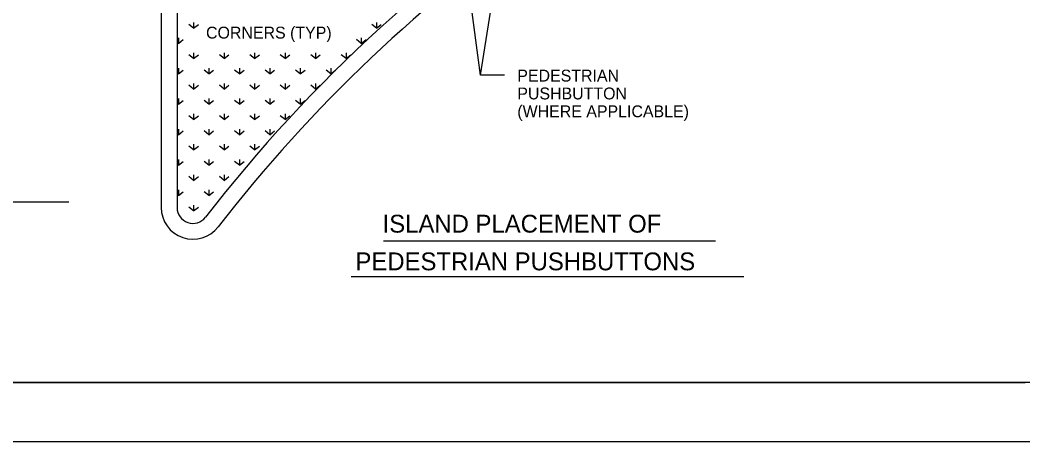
# Model space of a CAD drawing. Extents: x 36 to 940, y -1166 to 1210.
# Drawn here: x 408.6 to 661.3, y -1165.8 to -1059.4 of the extents above; entities that cross this region are included whole.
import ezdxf

# ---------------------------------------------------------------- set-up
doc = ezdxf.new("R2010")
doc.units = 0
for name, color, linetype in [('1', 7, 'Continuous'), ('2', 7, 'Continuous'), ('Default', 7, 'Continuous'), ('PLT-BNDY', 7, 'Continuous')]:
    doc.layers.add(name, color=color, linetype=linetype)

msp = doc.modelspace()

# ---------------------------------------------------------------- linework, layer by layer
at = {"layer": '1'}
for p, q in [((861.86, -1150.83), (75.86, -1150.83)), ((75.86, -1150.83), (661.86, -1150.83))]:
    msp.add_line(p, q, dxfattribs=at)
at = {"layer": '2'}
for p, q in [((524.67, -1073.35), (538.81, -984.29)), ((524.67, -1073.35), (519.57, -1035.44)), ((277.32, -1105.31), (420.95, -1105.31)), ((500.24, -1115.13), (583.82, -1115.13)), ((492.05, -1124.14), (590.98, -1124.14))]:
    msp.add_line(p, q, dxfattribs=at)
at = {"layer": 'Default'}
for p, q in [((444.2, -994.91), (444.2, -1106.71)), ((448.2, -1002.91), (448.2, -1106.71)), ((452.36, -1061.48), (451.16, -1060.52)), ((452.36, -1060.04), (452.36, -1061.48)), ((452.36, -1061.48), (453.56, -1060.52)), ((498.44, -1061.48), (497.24, -1060.52)), ((498.44, -1060.04), (498.44, -1061.48)), ((498.44, -1061.48), (499.64, -1060.52)), ((448.52, -1065.32), (448.2, -1065.07)), ((448.52, -1063.88), (448.52, -1065.32)), ((448.52, -1065.32), (449.72, -1064.36)), ((494.6, -1065.32), (493.4, -1064.36)), ((494.6, -1063.88), (494.6, -1065.32)), ((494.6, -1065.32), (495.8, -1064.36)), ((452.36, -1069.16), (451.16, -1068.2)), ((452.36, -1067.72), (452.36, -1069.16)), ((452.36, -1069.16), (453.56, -1068.2)), ((460.04, -1069.16), (458.84, -1068.2)), ((460.04, -1067.72), (460.04, -1069.16)), ((460.04, -1069.16), (461.24, -1068.2)), ((467.72, -1069.16), (466.52, -1068.2)), ((467.72, -1067.72), (467.72, -1069.16)), ((467.72, -1069.16), (468.92, -1068.2)), ((475.4, -1069.16), (474.2, -1068.2)), ((475.4, -1067.72), (475.4, -1069.16)), ((475.4, -1069.16), (476.6, -1068.2)), ((483.08, -1069.16), (481.88, -1068.2)), ((483.08, -1067.72), (483.08, -1069.16)), ((483.08, -1069.16), (484.28, -1068.2)), ((490.76, -1069.16), (489.56, -1068.2)), ((490.76, -1067.72), (490.76, -1069.16)), ((490.76, -1069.16), (491.96, -1068.2)), ((448.52, -1073), (448.2, -1072.75)), ((448.52, -1071.56), (448.52, -1073)), ((448.52, -1073), (449.72, -1072.04)), ((456.2, -1073), (455, -1072.04)), ((456.2, -1071.56), (456.2, -1073)), ((456.2, -1073), (457.4, -1072.04)), ((463.88, -1073), (462.68, -1072.04)), ((463.88, -1071.56), (463.88, -1073)), ((463.88, -1073), (465.08, -1072.04)), ((471.56, -1073), (470.36, -1072.04)), ((471.56, -1071.56), (471.56, -1073)), ((471.56, -1073), (472.76, -1072.04)), ((479.24, -1073), (478.04, -1072.04)), ((479.24, -1071.56), (479.24, -1073)), ((479.24, -1073), (480.44, -1072.04)), ((486.92, -1073), (485.72, -1072.04)), ((486.92, -1071.56), (486.92, -1073)), ((486.92, -1073), (488.12, -1072.04)), ((530.67, -1073.35), (524.67, -1073.35)), ((452.36, -1076.84), (451.16, -1075.88)), ((452.36, -1075.4), (452.36, -1076.84)), ((452.36, -1076.84), (453.56, -1075.88)), ((460.04, -1076.84), (458.84, -1075.88)), ((460.04, -1075.4), (460.04, -1076.84)), ((460.04, -1076.84), (461.24, -1075.88)), ((467.72, -1076.84), (466.52, -1075.88)), ((467.72, -1075.4), (467.72, -1076.84)), ((467.72, -1076.84), (468.92, -1075.88)), ((475.4, -1076.84), (474.2, -1075.88)), ((475.4, -1075.4), (475.4, -1076.84)), ((475.4, -1076.84), (476.6, -1075.88)), ((483.08, -1076.84), (481.88, -1075.88)), ((483.08, -1075.4), (483.08, -1076.84)), ((483.08, -1076.84), (484.28, -1075.88)), ((448.52, -1080.68), (448.2, -1080.43)), ((448.52, -1079.24), (448.52, -1080.68)), ((448.52, -1080.68), (449.72, -1079.72)), ((456.2, -1080.68), (455, -1079.72)), ((456.2, -1079.24), (456.2, -1080.68)), ((456.2, -1080.68), (457.4, -1079.72)), ((463.88, -1080.68), (462.68, -1079.72)), ((463.88, -1079.24), (463.88, -1080.68)), ((463.88, -1080.68), (465.08, -1079.72)), ((471.56, -1080.68), (470.36, -1079.72)), ((471.56, -1079.24), (471.56, -1080.68)), ((471.56, -1080.68), (472.76, -1079.72)), ((479.24, -1080.68), (478.04, -1079.72)), ((479.24, -1079.24), (479.24, -1080.68)), ((479.24, -1080.68), (480.44, -1079.72)), ((452.36, -1084.52), (451.16, -1083.56)), ((452.36, -1083.08), (452.36, -1084.52)), ((452.36, -1084.52), (453.56, -1083.56)), ((460.04, -1084.52), (458.84, -1083.56)), ((460.04, -1083.08), (460.04, -1084.52)), ((460.04, -1084.52), (461.24, -1083.56)), ((467.72, -1084.52), (466.52, -1083.56)), ((467.72, -1083.08), (467.72, -1084.52)), ((467.72, -1084.52), (468.92, -1083.56)), ((475.4, -1084.52), (474.2, -1083.56)), ((475.4, -1083.08), (475.4, -1084.52)), ((475.4, -1084.52), (476.6, -1083.56)), ((448.52, -1088.36), (448.2, -1088.11)), ((448.52, -1086.92), (448.52, -1088.36)), ((448.52, -1088.36), (449.72, -1087.4)), ((456.2, -1088.36), (455, -1087.4)), ((456.2, -1086.92), (456.2, -1088.36)), ((456.2, -1088.36), (457.4, -1087.4)), ((463.88, -1088.36), (462.68, -1087.4)), ((463.88, -1086.92), (463.88, -1088.36)), ((463.88, -1088.36), (465.08, -1087.4)), ((471.56, -1088.36), (470.36, -1087.4)), ((471.56, -1086.92), (471.56, -1088.36)), ((471.56, -1088.36), (472.76, -1087.4)), ((452.36, -1092.2), (451.16, -1091.24)), ((452.36, -1090.76), (452.36, -1092.2)), ((452.36, -1092.2), (453.56, -1091.24)), ((460.04, -1092.2), (458.84, -1091.24)), ((460.04, -1090.76), (460.04, -1092.2)), ((460.04, -1092.2), (461.24, -1091.24)), ((467.72, -1092.2), (466.52, -1091.24)), ((467.72, -1090.76), (467.72, -1092.2)), ((467.72, -1092.2), (468.92, -1091.24)), ((448.52, -1096.04), (448.2, -1095.79)), ((448.52, -1094.6), (448.52, -1096.04)), ((448.52, -1096.04), (449.72, -1095.08)), ((456.2, -1096.04), (455, -1095.08)), ((456.2, -1094.6), (456.2, -1096.04)), ((456.2, -1096.04), (457.4, -1095.08)), ((463.88, -1096.04), (462.68, -1095.08)), ((463.88, -1094.6), (463.88, -1096.04)), ((463.88, -1096.04), (465.08, -1095.08)), ((452.36, -1099.88), (451.16, -1098.92)), ((452.36, -1098.44), (452.36, -1099.88)), ((452.36, -1099.88), (453.56, -1098.92)), ((460.04, -1099.88), (458.84, -1098.92)), ((460.04, -1098.44), (460.04, -1099.88)), ((460.04, -1099.88), (461.24, -1098.92)), ((448.52, -1103.72), (448.2, -1103.47)), ((448.52, -1102.28), (448.52, -1103.72)), ((448.52, -1103.72), (449.72, -1102.76)), ((456.2, -1103.72), (455, -1102.76)), ((456.2, -1102.28), (456.2, -1103.72)), ((456.2, -1103.72), (457.4, -1102.76)), ((452.36, -1107.56), (451.16, -1106.6)), ((452.36, -1106.12), (452.36, -1107.56)), ((452.36, -1107.56), (453.56, -1106.6))]:
    msp.add_line(p, q, dxfattribs=at)
for centre, radius, start, end in [((753.46, -1339.64), 376.8, 122.5261, 142.2884), ((753.46, -1339.64), 372.8, 124.6158, 142.2884), ((452.2, -1106.71), 8, 180, 322.2884), ((452.2, -1106.71), 4, 180, 322.2884)]:
    msp.add_arc(centre, radius, start, end, dxfattribs=at)
at = {"layer": 'PLT-BNDY'}
msp.add_lwpolyline([(35.86, -571.83), (876.86, -571.83), (876.86, -1165.83), (35.86, -1165.83)], close=True, dxfattribs=at)

# ---------------------------------------------------------------- texts
at = {"layer": '2'}
for s, p in [('ISLAND PLACEMENT OF', (499.98, -1113.04)), ('PEDESTRIAN PUSHBUTTONS', (493.14, -1122.54))]:
    msp.add_text(s, height=4.5, dxfattribs=at).set_placement(p)
at = {"layer": 'Default'}
for s, p in [('CORNERS (TYP)', (455.49, -1064.11)), ('PEDESTRIAN', (533.92, -1074.95)), ('PUSHBUTTON', (533.92, -1079.45)), ('(WHERE APPLICABLE)', (533.92, -1083.95))]:
    msp.add_text(s, height=3, dxfattribs=at).set_placement(p)

doc.saveas('drawing.dxf')
